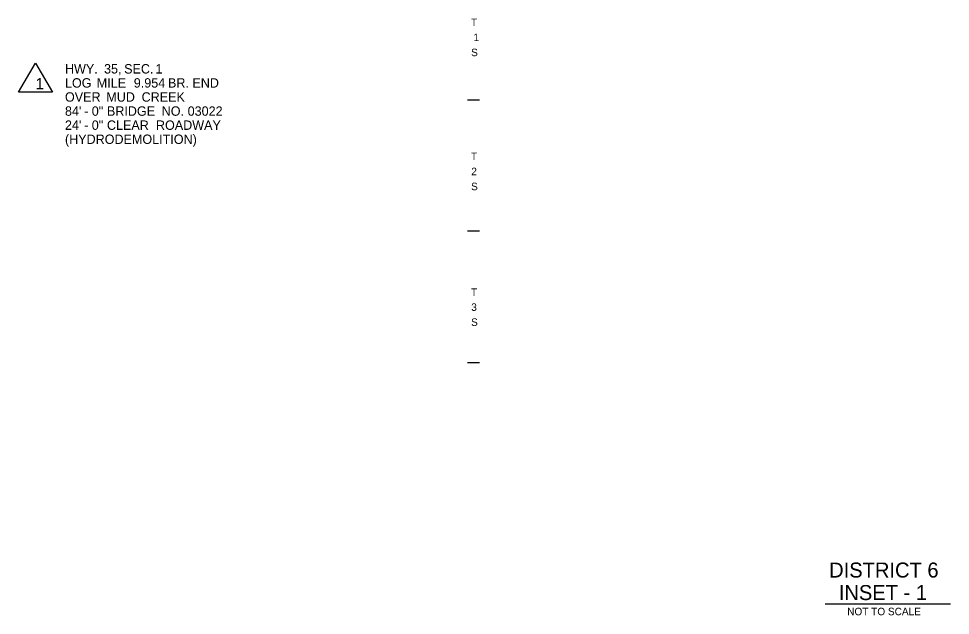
# Model space of a CAD drawing. Extents: x -33639 to 34530, y -17264 to 5867.
# Drawn here: x -17073 to -9631, y -3958 to 809 of the extents above; entities that cross this region are included whole.
import ezdxf

# ---------------------------------------------------------------- set-up
doc = ezdxf.new("R2010")
doc.units = 0
for name, color, linetype in [('2', 7, 'Continuous'), ('Default', 7, 'Continuous'), ('R_Annotation', 7, 'Continuous'), ('S_MISC_BOUNDARY', 7, 'Continuous')]:
    doc.layers.add(name, color=color, linetype=linetype)

msp = doc.modelspace()

# ---------------------------------------------------------------- linework, layer by layer
at = {"layer": 'Default'}
for p, q in [((-13392.9, 156.8), (-13487.9, 156.8)), ((-13393.3, -888.6), (-13488.3, -888.6)), ((-13393.3, -1941.5), (-13488.3, -1941.5))]:
    msp.add_line(p, q, dxfattribs=at)
at = {"layer": 'R_Annotation'}
msp.add_line((-10631.4, -3866.6), (-9631.4, -3866.6), dxfattribs=at)
msp.add_lwpolyline([(-16938, 454.5), (-16803, 220.6), (-17073, 220.6)], close=True, dxfattribs=at)
at = {"layer": 'S_MISC_BOUNDARY'}
msp.add_line((-16703, 445.6), (-16703, 445.6), dxfattribs=at)

# ---------------------------------------------------------------- texts
at = {"layer": '2'}
for s, p in [('T', (-13460.4, 749.1)), ('1', (-13440.8, 629.1)), ('S', (-13459.3, 509.1)), ('T', (-13460.4, -321.6)), ('2', (-13457.8, -441.6)), ('S', (-13459.3, -561.6)), ('T', (-13460.4, -1405.7)), ('3', (-13457.8, -1525.7)), ('S', (-13459.3, -1645.7))]:
    msp.add_text(s, height=60, dxfattribs=at).set_placement(p)
at = {"layer": 'Default'}
for s, p in [(' 35,', (-16418.7, 370.6)), (' SEC.', (-16258.2, 370.6)), ('HWY.', (-16703, 370.6)), (' 1', (-16007.6, 370.6)), ('LOG', (-16703, 258.1)), (' MILE', (-16477.1, 258.1)), (' 9.954', (-16181.3, 258.1)), (' BR.', (-15908.1, 258.1)), (' END', (-15712.9, 258.1)), ('OVER', (-16703, 145.6)), (' MUD', (-16400.6, 145.6)), (' CREEK', (-16118.7, 145.6)), ("84'", (-16703, 33.1)), (' 0"', (-16516.7, 33.1)), (' BRIDGE', (-16395.7, 33.1)), (' NO.', (-15958.4, 33.1)), (' 03022', (-15750.9, 33.1)), (' -', (-16576.9, 33.1)), ("24'", (-16703, -79.4)), (' -', (-16576.9, -79.4)), (' 0"', (-16516.7, -79.4)), (' CLEAR', (-16395.7, -79.4)), (' ROADWAY', (-16004.1, -79.4)), ('(HYDRODEMOLITION)', (-16703, -191.9))]:
    msp.add_text(s, height=75, dxfattribs=at).set_placement(p)
at = {"layer": 'R_Annotation'}
for s, height, p in [('1', 90, (-16937.9, 244)), ('DISTRICT 6', 120, (-10599.5, -3656)), ('INSET - 1', 120, (-10522.5, -3836)), ('NOT TO SCALE', 60, (-10455.4, -3957.3))]:
    msp.add_text(s, height=height, dxfattribs=at).set_placement(p)

doc.saveas('drawing.dxf')
